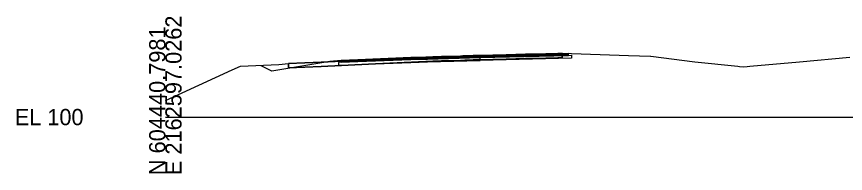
# Model space of a CAD drawing. Extents: x -26 to 1303, y -10 to 12033.
# Drawn here: x 974.3 to 1117.4, y 990.3 to 1017.3 of the extents above; entities that cross this region are included whole.
import ezdxf

# ---------------------------------------------------------------- set-up
doc = ezdxf.new("R2010")
doc.units = 0
for name, color, linetype in [('RD_GPK_XS_Cell', 7, 'Continuous'), ('RD_XS_Base', 7, 'Continuous'), ('RD_XS_ExGround', 7, 'Continuous'), ('RD_XS_ExPaveRet', 7, 'Continuous'), ('RD_XS_Greenside', 7, 'Continuous'), ('RD_XS_Pave', 7, 'Continuous'), ('RD_XS_PaveOvlay_CP', 7, 'Continuous'), ('RD_XS_TieSlope', 7, 'Continuous')]:
    doc.layers.add(name, color=color, linetype=linetype)

msp = doc.modelspace()

# ---------------------------------------------------------------- linework, layer by layer
at = {"layer": 'RD_GPK_XS_Cell'}
msp.add_line((1000, 1000), (1150, 1000), dxfattribs=at)
at = {"layer": 'RD_XS_Base'}
for p, q in [((1054.38, 1010.23), (1070.12, 1010.64)), ((1069.62, 1010.62), (1069.62, 1010.62)), ((1070.12, 1010.64), (1070.12, 1010.14)), ((1070.12, 1010.6), (1070.12, 1010.6)), ((1030, 1009.42), (1029.88, 1009.41)), ((1029.88, 1009.41), (1029.88, 1009.03)), ((1029.88, 1009.03), (1029.88, 1008.91)), ((1030.38, 1009.43), (1030, 1009.42)), ((1033.24, 1009.55), (1030.38, 1009.43)), ((1030.38, 1008.93), (1033.24, 1009.05)), ((1042.38, 1009.91), (1033.24, 1009.55)), ((1033.24, 1009.05), (1042.38, 1009.41)), ((1045.27, 1009.99), (1042.38, 1009.91)), ((1042.38, 1009.41), (1045.27, 1009.49)), ((1054.38, 1010.23), (1045.27, 1009.99)), ((1045.27, 1009.49), (1054.38, 1009.73)), ((1054.38, 1009.73), (1054.38, 1010.39)), ((1054.38, 1010.39), (1054.38, 1010.39)), ((1054.38, 1010.39), (1054.38, 1010.39)), ((1054.38, 1010.39), (1054.38, 1010.23)), ((1054.38, 1010.23), (1054.38, 1010.23)), ((1054.38, 1009.73), (1054.38, 1010.23)), ((1054.38, 1010.23), (1054.38, 1010.23)), ((1054.38, 1010.23), (1054.38, 1010.23)), ((1070.12, 1010.14), (1054.38, 1009.73)), ((1054.38, 1009.73), (1054.38, 1009.73)), ((1029.88, 1008.91), (1030, 1008.92)), ((1030, 1008.92), (1030.38, 1008.93))]:
    msp.add_line(p, q, dxfattribs=at)
at = {"layer": 'RD_XS_ExGround'}
msp.add_lwpolyline([(1000, 1002.84), (1011.55, 1008.12), (1012.98, 1008.77), (1019.62, 1009.06), (1021.24, 1009.22), (1026.91, 1009.48), (1046.34, 1010.38), (1046.76, 1010.36), (1047.4, 1010.4), (1050.94, 1010.5), (1051.73, 1010.53), (1053.17, 1010.58), (1055.09, 1010.63), (1056.54, 1010.64), (1062.21, 1010.81), (1066.18, 1010.88), (1068.53, 1010.98), (1079.97, 1010.63), (1081.86, 1010.57), (1083.74, 1010.5), (1083.79, 1010.49), (1083.83, 1010.49), (1091.44, 1009.49), (1098.87, 1008.75), (1099.15, 1008.72), (1099.75, 1008.66), (1100.46, 1008.73), (1100.93, 1008.77), (1109.48, 1009.5), (1118.19, 1010.3)], dxfattribs=at)
at = {"layer": 'RD_XS_ExPaveRet'}
for points in [[(1068.25, 1010.96), (1068.53, 1010.98), (1068.53, 1010.49), (1068.53, 1010.23), (1068.25, 1010.21), (1067.77, 1010.21), (1065.7, 1010.12), (1062.21, 1010.06), (1058.87, 1009.96), (1056.54, 1009.89), (1055.94, 1009.88), (1055.09, 1009.88), (1053.53, 1009.84), (1053.17, 1009.83), (1052.89, 1009.82), (1051.73, 1009.78), (1051.36, 1009.77), (1050.94, 1009.75), (1049.06, 1009.7), (1047.7, 1009.66), (1047.01, 1009.61), (1046.84, 1009.61), (1046.76, 1009.61), (1046.31, 1009.63), (1046.19, 1009.62), (1035.07, 1009.11), (1026.92, 1008.73), (1021.24, 1008.47), (1021.24, 1008.47), (1021.24, 1008.47), (1021.24, 1008.47), (1021.24, 1008.47), (1021.24, 1008.47), (1021.24, 1008.7), (1021.24, 1009.22), (1021.24, 1009.22), (1021.24, 1009.22), (1021.24, 1009.22), (1021.24, 1009.22), (1021.24, 1009.22), (1026.92, 1009.48), (1035.07, 1009.86), (1046.19, 1010.37), (1046.31, 1010.38), (1046.76, 1010.36), (1046.84, 1010.36), (1047.01, 1010.36), (1047.7, 1010.41), (1049.06, 1010.45), (1050.94, 1010.5), (1051.36, 1010.52), (1051.73, 1010.53), (1052.89, 1010.57), (1053.17, 1010.58), (1053.53, 1010.59), (1055.09, 1010.63), (1055.94, 1010.63), (1056.54, 1010.64), (1058.87, 1010.71), (1062.21, 1010.81), (1065.7, 1010.87), (1067.77, 1010.96), (1068.25, 1010.96)], [(1067.77, 1010.96), (1065.7, 1010.87), (1062.21, 1010.81), (1058.87, 1010.71), (1056.54, 1010.64), (1055.94, 1010.63), (1055.09, 1010.63), (1053.53, 1010.59), (1053.17, 1010.58), (1052.89, 1010.57), (1051.73, 1010.53), (1051.36, 1010.52), (1050.94, 1010.5), (1049.06, 1010.45), (1047.7, 1010.41), (1047.01, 1010.36), (1046.84, 1010.36), (1046.76, 1010.36), (1046.31, 1010.38), (1046.19, 1010.37), (1035.07, 1009.86), (1026.92, 1009.48), (1021.24, 1009.22), (1021.24, 1009.22), (1021.24, 1009.22), (1021.24, 1009.22), (1021.24, 1009.22), (1021.24, 1008.7), (1021.24, 1008.47), (1021.24, 1008.47), (1021.24, 1008.47), (1021.24, 1008.47), (1021.24, 1008.47), (1026.92, 1008.73), (1035.07, 1009.11), (1046.19, 1009.62), (1046.31, 1009.63), (1046.76, 1009.61), (1046.84, 1009.61), (1047.01, 1009.61), (1047.7, 1009.66), (1049.06, 1009.7), (1050.94, 1009.75), (1051.36, 1009.77), (1051.73, 1009.78), (1052.89, 1009.82), (1053.17, 1009.83), (1053.53, 1009.84), (1055.09, 1009.88), (1055.94, 1009.88), (1056.54, 1009.89), (1058.87, 1009.96), (1062.21, 1010.06), (1065.7, 1010.12), (1067.77, 1010.21), (1068.25, 1010.21), (1068.53, 1010.23), (1068.53, 1010.49), (1068.53, 1010.98), (1068.25, 1010.96), (1067.77, 1010.96)]]:
    msp.add_lwpolyline(points, dxfattribs=at)
at = {"layer": 'RD_XS_Greenside'}
for p, q in [((1028.38, 1009.59), (1018.38, 1007.93)), ((1018.38, 1007.93), (1016.55, 1008.84))]:
    msp.add_line(p, q, dxfattribs=at)
at = {"layer": 'RD_XS_Pave'}
for p, q in [((1054.38, 1010.54), (1045.27, 1010.31)), ((1069.62, 1010.94), (1054.38, 1010.54)), ((1069.62, 1010.78), (1054.38, 1010.39)), ((1054.38, 1010.39), (1069.62, 1010.78)), ((1054.38, 1010.23), (1069.62, 1010.62)), ((1054.38, 1010.54), (1054.38, 1010.54)), ((1069.62, 1010.78), (1069.62, 1010.94)), ((1069.62, 1010.94), (1069.62, 1010.94)), ((1069.62, 1010.62), (1069.62, 1010.78)), ((1069.62, 1010.78), (1069.62, 1010.78)), ((1033.24, 1009.87), (1030.38, 1009.75)), ((1030.38, 1009.75), (1030.38, 1009.63)), ((1030.38, 1009.59), (1033.24, 1009.71)), ((1033.24, 1009.71), (1030.38, 1009.59)), ((1030.38, 1009.63), (1030.38, 1009.59)), ((1030.38, 1009.59), (1030.38, 1009.47)), ((1030.38, 1009.43), (1033.24, 1009.55)), ((1030.38, 1009.47), (1030.38, 1009.43)), ((1042.38, 1010.23), (1033.24, 1009.87)), ((1033.24, 1009.71), (1042.38, 1010.07)), ((1042.38, 1010.07), (1033.24, 1009.71)), ((1033.24, 1009.55), (1042.38, 1009.91)), ((1045.27, 1010.31), (1042.38, 1010.23)), ((1042.38, 1010.07), (1045.27, 1010.15)), ((1045.27, 1010.15), (1042.38, 1010.07)), ((1042.38, 1009.91), (1045.27, 1009.99)), ((1045.27, 1010.15), (1054.38, 1010.39)), ((1054.38, 1010.39), (1045.27, 1010.15)), ((1045.27, 1009.99), (1054.38, 1010.23)), ((1054.38, 1010.39), (1054.38, 1010.39)), ((1054.38, 1010.39), (1054.38, 1010.39)), ((1054.38, 1010.39), (1054.38, 1010.23)), ((1054.38, 1010.39), (1054.38, 1010.39)), ((1054.38, 1010.23), (1054.38, 1010.39)), ((1054.38, 1010.39), (1054.38, 1010.39)), ((1054.38, 1010.39), (1054.38, 1010.39)), ((1054.38, 1010.23), (1054.38, 1010.23)), ((1054.38, 1010.23), (1054.38, 1010.23))]:
    msp.add_line(p, q, dxfattribs=at)
at = {"layer": 'RD_XS_PaveOvlay_CP'}
for p, q in [((1054.38, 1010.54), (1045.27, 1010.31)), ((1069.62, 1010.94), (1054.38, 1010.54)), ((1054.38, 1010.54), (1054.38, 1010.54)), ((1033.24, 1009.87), (1030.38, 1009.75)), ((1042.38, 1010.23), (1033.24, 1009.87)), ((1045.27, 1010.31), (1042.38, 1010.23))]:
    msp.add_line(p, q, dxfattribs=at)
at = {"layer": 'RD_XS_TieSlope'}
msp.add_line((1030.38, 1009.75), (1028.38, 1009.59), dxfattribs=at)

# ---------------------------------------------------------------- texts
at = {"layer": 'RD_GPK_XS_Cell'}
for s, p in [('E 2162597.0262', (1002.8, 990)), ('N 604440.7981', (1000, 990))]:
    msp.add_text(s, height=2.8, rotation=90, dxfattribs=at).set_placement(p)
msp.add_text('EL 100', height=2.8, dxfattribs=at).set_placement((974, 998.6))

doc.saveas('drawing.dxf')
